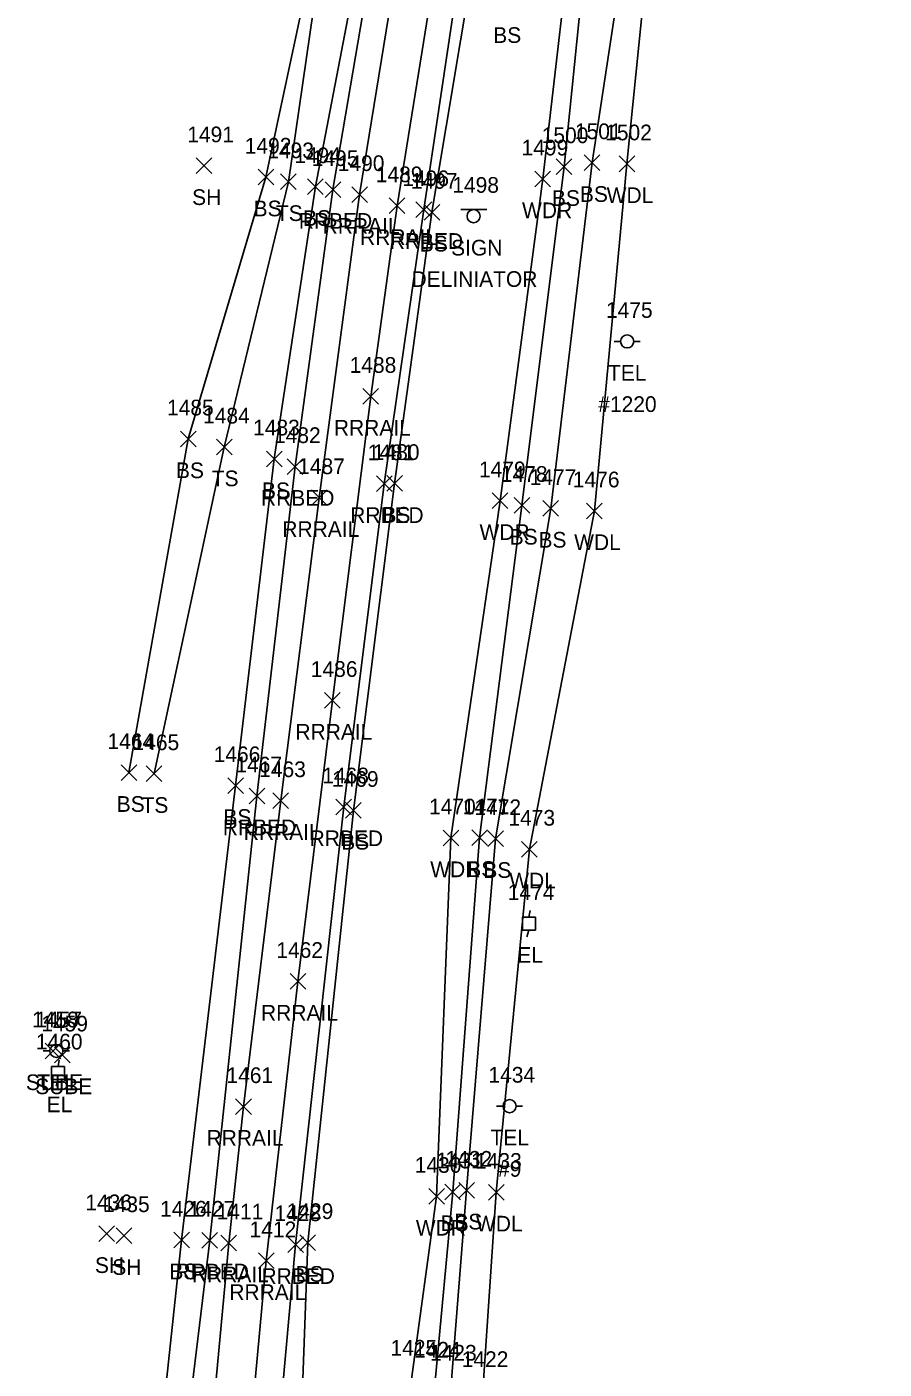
# Model space of a CAD drawing. Extents: x 1769141 to 1770817, y 735471 to 742405.
# Drawn here: x 1770142.5 to 1770251.8, y 741653.9 to 741825.1 of the extents above; entities that cross this region are included whole.
import ezdxf

# ---------------------------------------------------------------- set-up
doc = ezdxf.new("R2010")
doc.units = 0
for name, color, linetype in [('L_A', 7, 'Continuous'), ('L_I', 7, 'Continuous'), ('L_TIC', 7, 'Continuous'), ('LAWA', 7, 'Continuous'), ('LELB', 7, 'Continuous'), ('R_A', 7, 'Continuous'), ('R_I', 7, 'Continuous'), ('R_TIC', 7, 'Continuous'), ('RR', 7, 'Continuous'), ('RRB', 7, 'Continuous'), ('S_A', 7, 'Continuous'), ('S_C', 7, 'Continuous'), ('S_I', 7, 'Continuous'), ('SSGN', 7, 'Continuous'), ('U_A', 7, 'Continuous'), ('U_C', 7, 'Continuous'), ('U_I', 7, 'Continuous'), ('U_TIC', 7, 'Continuous'), ('UEPT', 7, 'Continuous'), ('UP', 7, 'Continuous')]:
    doc.layers.add(name, color=color, linetype=linetype)

msp = doc.modelspace()

# ---------------------------------------------------------------- linework, layer by layer
at = {"layer": 'L_TIC'}
for points in [[(1770213.61, 741806.75), (1770215.61, 741808.75)], [(1770215.61, 741806.75), (1770213.61, 741808.75)], [(1770164.12, 741806.35), (1770166.12, 741808.35)], [(1770166.12, 741806.35), (1770164.12, 741808.35)], [(1770210.04, 741806.24), (1770212.04, 741808.24)], [(1770212.04, 741806.24), (1770210.04, 741808.24)], [(1770218.05, 741806.6), (1770220.05, 741808.6)], [(1770220.05, 741806.6), (1770218.05, 741808.6)], [(1770172.01, 741804.91), (1770174.01, 741806.91)], [(1770174.01, 741804.91), (1770172.01, 741806.91)], [(1770174.88, 741804.31), (1770176.88, 741806.31)], [(1770176.88, 741804.31), (1770174.88, 741806.31)], [(1770178.32, 741803.69), (1770180.32, 741805.69)], [(1770180.32, 741803.69), (1770178.32, 741805.69)], [(1770207.31, 741804.67), (1770209.31, 741806.67)], [(1770209.31, 741804.67), (1770207.31, 741806.67)], [(1770193.19, 741800.42), (1770195.19, 741802.42)], [(1770195.19, 741800.42), (1770193.19, 741802.42)], [(1770162.11, 741771.52), (1770164.11, 741773.52)], [(1770164.11, 741771.52), (1770162.11, 741773.52)], [(1770166.7, 741770.49), (1770168.7, 741772.49)], [(1770168.7, 741770.49), (1770166.7, 741772.49)], [(1770173.08, 741768.97), (1770175.08, 741770.97)], [(1770175.08, 741768.97), (1770173.08, 741770.97)], [(1770188.43, 741765.84), (1770190.43, 741767.84)], [(1770190.43, 741765.84), (1770188.43, 741767.84)], [(1770201.88, 741763.64), (1770203.88, 741765.64)], [(1770203.88, 741763.64), (1770201.88, 741765.64)], [(1770204.66, 741763.05), (1770206.66, 741765.05)], [(1770206.66, 741763.05), (1770204.66, 741765.05)], [(1770208.33, 741762.66), (1770210.33, 741764.66)], [(1770210.33, 741762.66), (1770208.33, 741764.66)], [(1770213.9, 741762.35), (1770215.9, 741764.35)], [(1770215.9, 741762.35), (1770213.9, 741764.35)], [(1770154.56, 741728.97), (1770156.56, 741730.97)], [(1770156.56, 741728.97), (1770154.56, 741730.97)], [(1770157.75, 741728.84), (1770159.75, 741730.84)], [(1770159.75, 741728.84), (1770157.75, 741730.84)], [(1770168.16, 741727.31), (1770170.16, 741729.31)], [(1770170.16, 741727.31), (1770168.16, 741729.31)], [(1770183.18, 741724.16), (1770185.18, 741726.16)], [(1770185.18, 741724.16), (1770183.18, 741726.16)], [(1770195.6, 741720.64), (1770197.6, 741722.64)], [(1770197.6, 741720.64), (1770195.6, 741722.64)], [(1770199.25, 741720.67), (1770201.25, 741722.67)], [(1770201.25, 741720.67), (1770199.25, 741722.67)], [(1770201.3, 741720.55), (1770203.3, 741722.55)], [(1770203.3, 741720.55), (1770201.3, 741722.55)], [(1770205.62, 741719.21), (1770207.62, 741721.21)], [(1770207.62, 741719.21), (1770205.62, 741721.21)], [(1770193.77, 741674.94), (1770195.77, 741676.94)], [(1770195.77, 741674.94), (1770193.77, 741676.94)], [(1770195.84, 741675.51), (1770197.84, 741677.51)], [(1770197.84, 741675.51), (1770195.84, 741677.51)], [(1770197.6, 741675.72), (1770199.6, 741677.72)], [(1770199.6, 741675.72), (1770197.6, 741677.72)], [(1770201.39, 741675.46), (1770203.39, 741677.46)], [(1770203.39, 741675.46), (1770201.39, 741677.46)], [(1770151.73, 741670.17), (1770153.73, 741672.17)], [(1770153.73, 741670.17), (1770151.73, 741672.17)], [(1770153.94, 741669.93), (1770155.94, 741671.93)], [(1770155.94, 741669.93), (1770153.94, 741671.93)], [(1770161.27, 741669.36), (1770163.27, 741671.36)], [(1770163.27, 741669.36), (1770161.27, 741671.36)], [(1770177.36, 741669.05), (1770179.36, 741671.05)], [(1770179.36, 741669.05), (1770177.36, 741671.05)]]:
    msp.add_lwpolyline(points, dxfattribs=at)
at = {"layer": 'LAWA'}
for points in [[(1770200.67, 741651.18), (1770196.63, 741652), (1770194.58, 741652.38), (1770191.59, 741652.63), (1770194.77, 741675.94), (1770196.6, 741721.64), (1770202.88, 741764.64), (1770208.31, 741805.67), (1770212.68, 741843.55)], [(1770200.67, 741651.18), (1770202.39, 741676.46), (1770206.62, 741720.21), (1770214.9, 741763.35), (1770219.05, 741807.6), (1770222.48, 741841.68), (1770219.97, 741843.04), (1770214.71, 741843.41), (1770212.68, 741843.55)]]:
    msp.add_lwpolyline(points, dxfattribs=at)
at = {"layer": 'LELB'}
for points in [[(1770189.51, 741370.79), (1770192.33, 741421.87), (1770190.52, 741443.62), (1770191.25, 741465.52), (1770192.9, 741467.86), (1770192.23, 741494.22), (1770193.26, 741543.26), (1770192.21, 741598.2), (1770194.88, 741636.38), (1770196.63, 741652), (1770198.6, 741676.72), (1770202.3, 741721.55), (1770209.33, 741763.66), (1770214.61, 741807.75), (1770219.97, 741843.04), (1770223.09, 741876.08), (1770226.05, 741889.39), (1770243.39, 741887.35), (1770251.84, 741882.91)], [(1770189.82, 741481.43), (1770190.88, 741494.18), (1770191.42, 741543.22), (1770190.92, 741598.66), (1770192.66, 741636.32), (1770194.58, 741652.38), (1770196.84, 741676.51), (1770200.25, 741721.67), (1770205.66, 741764.05), (1770211.04, 741807.24), (1770214.71, 741843.41), (1770218.13, 741875.72), (1770220.67, 741890.47)], [(1770159.47, 741122.16), (1770155.88, 741129.72), (1770152.26, 741191.83), (1770148.79, 741250.94), (1770147.9, 741304.26), (1770146.46, 741364.5), (1770147.88, 741419.38), (1770149.7, 741479.08), (1770152.69, 741545.1), (1770155.76, 741599.64), (1770158.96, 741639.34), (1770162.27, 741670.36), (1770169.16, 741728.31), (1770174.08, 741769.97), (1770179.32, 741804.69), (1770187.63, 741847.88), (1770194.61, 741886.57)], [(1770170.72, 741118.89), (1770170.78, 741142.85), (1770168.08, 741192.95), (1770167.14, 741250.65), (1770163.56, 741305.09), (1770162.91, 741364.69), (1770162.95, 741418.42), (1770164.45, 741477.75), (1770168.47, 741544.61), (1770171.96, 741598.42), (1770177.16, 741637.54), (1770178.36, 741670.05), (1770184.18, 741725.16), (1770189.43, 741766.84), (1770194.19, 741801.42), (1770201.5, 741845.17), (1770207.42, 741883.86)], [(1770155.56, 741729.97), (1770163.11, 741772.52), (1770173.01, 741805.91), (1770182.25, 741849.08)], [(1770158.75, 741729.84), (1770167.7, 741771.49), (1770175.88, 741805.31), (1770182.25, 741849.08)]]:
    msp.add_lwpolyline(points, dxfattribs=at)
at = {"layer": 'R_TIC'}
for points in [[(1770180.57, 741803.32), (1770182.57, 741805.32)], [(1770182.57, 741803.32), (1770180.57, 741805.32)], [(1770183.96, 741802.68), (1770185.96, 741804.68)], [(1770185.96, 741802.68), (1770183.96, 741804.68)], [(1770188.73, 741801.26), (1770190.73, 741803.26)], [(1770190.73, 741801.26), (1770188.73, 741803.26)], [(1770192.15, 741800.76), (1770194.15, 741802.76)], [(1770194.15, 741800.76), (1770192.15, 741802.76)], [(1770185.38, 741776.95), (1770187.38, 741778.95)], [(1770187.38, 741776.95), (1770185.38, 741778.95)], [(1770175.74, 741768), (1770177.74, 741770)], [(1770177.74, 741768), (1770175.74, 741770)], [(1770187.11, 741765.81), (1770189.11, 741767.81)], [(1770189.11, 741765.81), (1770187.11, 741767.81)], [(1770178.82, 741764.03), (1770180.82, 741766.03)], [(1770180.82, 741764.03), (1770178.82, 741766.03)], [(1770180.49, 741738.18), (1770182.49, 741740.18)], [(1770182.49, 741738.18), (1770180.49, 741740.18)], [(1770170.87, 741725.99), (1770172.87, 741727.99)], [(1770172.87, 741725.99), (1770170.87, 741727.99)], [(1770173.9, 741725.4), (1770175.9, 741727.4)], [(1770175.9, 741725.4), (1770173.9, 741727.4)], [(1770181.94, 741724.6), (1770183.94, 741726.6)], [(1770183.94, 741724.6), (1770181.94, 741726.6)], [(1770176.09, 741702.35), (1770178.09, 741704.35)], [(1770178.09, 741702.35), (1770176.09, 741704.35)], [(1770169.16, 741686.39), (1770171.16, 741688.39)], [(1770171.16, 741686.39), (1770169.16, 741688.39)], [(1770164.85, 741669.35), (1770166.85, 741671.35)], [(1770166.85, 741669.35), (1770164.85, 741671.35)], [(1770167.28, 741668.99), (1770169.28, 741670.99)], [(1770169.28, 741668.99), (1770167.28, 741670.99)], [(1770175.8, 741668.78), (1770177.8, 741670.78)], [(1770177.8, 741668.78), (1770175.8, 741670.78)], [(1770172.06, 741666.73), (1770174.06, 741668.73)], [(1770174.06, 741666.73), (1770172.06, 741668.73)]]:
    msp.add_lwpolyline(points, dxfattribs=at)
at = {"layer": 'RR'}
for points in [[(1770166.02, 741645.78), (1770168.28, 741669.99), (1770170.16, 741687.39), (1770174.9, 741726.4), (1770179.82, 741765.03), (1770184.96, 741803.68), (1770190.21, 741836.07), (1770195.69, 741868.56), (1770199.22, 741889.17), (1770209.87, 741946.53), (1770217, 741981.75), (1770223.18, 742009.88), (1770228.86, 742035.21), (1770233.42, 742054.72)], [(1770169.48, 741629), (1770173.06, 741667.73), (1770177.09, 741703.35), (1770181.49, 741739.18), (1770186.38, 741777.95), (1770189.73, 741802.26), (1770194.57, 741832.07), (1770199.51, 741861.73), (1770205.13, 741894.27), (1770209.73, 741919.85), (1770215.58, 741950.2), (1770216.86, 741956.06), (1770219.87, 741971.28), (1770226.9, 742003.73), (1770230.49, 742019.98), (1770231.83, 742026.33), (1770232.94, 742031.03), (1770234.04, 742035.58), (1770238.5, 742054.13)]]:
    msp.add_lwpolyline(points, dxfattribs=at)
at = {"layer": 'RRB'}
for points in [[(1770159.47, 741122.16), (1770157.22, 741138.41), (1770154.83, 741192.11), (1770151.88, 741250.64), (1770151.59, 741304.35), (1770150.34, 741364.24), (1770150.63, 741419.36), (1770151.12, 741479.07), (1770155.02, 741545.1), (1770158.66, 741599.97), (1770162.08, 741639.22), (1770165.85, 741670.35), (1770171.87, 741726.99), (1770176.74, 741769), (1770181.57, 741804.32), (1770188.88, 741847.51), (1770194.61, 741886.57), (1770198.24, 741898.62)], [(1770170.72, 741118.89), (1770169.25, 741143.07), (1770166.39, 741192.95), (1770164.02, 741250.29), (1770162.37, 741304.75), (1770161.63, 741364.62), (1770161.73, 741418.13), (1770163.48, 741477.78), (1770166.12, 741544.52), (1770169.96, 741598.79), (1770173.92, 741637.73), (1770176.8, 741669.78), (1770182.94, 741725.6), (1770188.11, 741766.81), (1770193.15, 741801.76), (1770199.69, 741845.61), (1770207.42, 741883.86)]]:
    msp.add_lwpolyline(points, dxfattribs=at)
at = {"layer": 'SSGN'}
for p, q in [((1770197.85, 741801.77), (1770201.18, 741801.77)), ((1770199.49, 741800.93), (1770199.49, 741800.93))]:
    msp.add_line(p, q, dxfattribs=at)
msp.add_circle((1770199.49, 741800.93), 0.833, dxfattribs=at)
at = {"layer": 'U_TIC'}
for points in [[(1770144.88, 741693.49), (1770146.88, 741695.49)], [(1770146.88, 741693.49), (1770144.88, 741695.49)], [(1770146.08, 741692.97), (1770148.08, 741694.97)], [(1770148.08, 741692.97), (1770146.08, 741694.97)]]:
    msp.add_lwpolyline(points, dxfattribs=at)
at = {"layer": 'UEPT'}
for p, q in [((1770205.71, 741709.88), (1770205.71, 741711.55)), ((1770205.71, 741711.55), (1770207.37, 741711.55)), ((1770206.71, 741712.38), (1770206.54, 741711.55)), ((1770207.37, 741711.55), (1770207.37, 741709.88)), ((1770207.37, 741709.88), (1770205.71, 741709.88)), ((1770206.29, 741709.05), (1770206.54, 741709.88)), ((1770206.54, 741710.72), (1770206.54, 741710.72)), ((1770145.68, 741690.83), (1770145.68, 741692.5)), ((1770145.68, 741692.5), (1770147.35, 741692.5)), ((1770146.68, 741693.33), (1770146.52, 741692.5)), ((1770147.35, 741692.5), (1770147.35, 741690.83)), ((1770147.35, 741690.83), (1770145.68, 741690.83)), ((1770146.27, 741690), (1770146.52, 741690.83)), ((1770146.52, 741691.67), (1770146.52, 741691.67))]:
    msp.add_line(p, q, dxfattribs=at)
at = {"layer": 'UP'}
for p, q in [((1770217.41, 741784.96), (1770218.23, 741784.96)), ((1770219.07, 741784.96), (1770219.07, 741784.96)), ((1770220.73, 741784.96), (1770219.9, 741784.96)), ((1770219.9, 741784.96), (1770219.9, 741784.96)), ((1770220.73, 741784.96), (1770220.73, 741784.96)), ((1770144.64, 741694.48), (1770145.47, 741694.48)), ((1770146.3, 741694.48), (1770146.3, 741694.48)), ((1770147.97, 741694.48), (1770147.13, 741694.48)), ((1770147.13, 741694.48), (1770147.13, 741694.48)), ((1770147.97, 741694.48), (1770147.97, 741694.48)), ((1770202.42, 741687.43), (1770203.24, 741687.43)), ((1770204.08, 741687.44), (1770204.08, 741687.44)), ((1770205.74, 741687.44), (1770204.91, 741687.44)), ((1770204.91, 741687.44), (1770204.91, 741687.44)), ((1770205.74, 741687.44), (1770205.74, 741687.44))]:
    msp.add_line(p, q, dxfattribs=at)
for centre in [(1770219.07, 741784.96), (1770146.3, 741694.48), (1770204.08, 741687.44)]:
    msp.add_circle(centre, 0.833, dxfattribs=at)

# ---------------------------------------------------------------- texts
at = {"layer": 'L_A'}
for s, p in [('BS', (1770202, 741823.02)), ('SH', (1770163.61, 741802.35)), ('BS', (1770209.48, 741802.24)), ('BS', (1770213.05, 741802.75)), ('WDL', (1770216.46, 741802.6)), ('BS', (1770171.45, 741800.91)), ('TS', (1770174.29, 741800.31)), ('WDR', (1770205.67, 741800.67)), ('BS', (1770177.76, 741799.69)), ('BS', (1770192.63, 741796.42)), ('BS', (1770161.55, 741767.52)), ('TS', (1770166.11, 741766.49)), ('BS', (1770172.52, 741764.97)), ('BS', (1770187.87, 741761.84)), ('WDR', (1770200.25, 741759.64)), ('BS', (1770204.1, 741759.05)), ('BS', (1770207.77, 741758.66)), ('WDL', (1770212.32, 741758.35)), ('BS', (1770154, 741724.97)), ('TS', (1770157.16, 741724.84)), ('BS', (1770167.6, 741723.31)), ('BS', (1770182.62, 741720.16)), ('WDR', (1770193.97, 741716.64)), ('BS', (1770198.69, 741716.67)), ('BS', (1770200.74, 741716.55)), ('WDL', (1770204.04, 741715.21)), ('BS', (1770195.28, 741671.51)), ('BS', (1770197.04, 741671.72)), ('WDL', (1770199.8, 741671.46)), ('WDR', (1770192.13, 741670.94)), ('SH', (1770151.22, 741666.17)), ('SH', (1770153.43, 741665.93)), ('BS', (1770160.71, 741665.36)), ('BS', (1770176.8, 741665.05))]:
    msp.add_text(s, height=2, dxfattribs=at).set_placement(p)
at = {"layer": 'L_I'}
for s, p in [('1491', (1770162.99, 741810.35)), ('1500', (1770208.18, 741810.24)), ('1501', (1770212.41, 741810.75)), ('1502', (1770216.27, 741810.6)), ('1492', (1770170.32, 741808.91)), ('1499', (1770205.61, 741808.67)), ('1493', (1770173.19, 741808.31)), ('1494', (1770176.63, 741807.69)), ('1497', (1770191.5, 741804.42)), ('1485', (1770160.41, 741775.52)), ('1484', (1770165.01, 741774.49)), ('1483', (1770171.39, 741772.97)), ('1480', (1770186.65, 741769.84)), ('1479', (1770200.18, 741767.64)), ('1478', (1770202.97, 741767.05)), ('1477', (1770206.64, 741766.66)), ('1476', (1770212.15, 741766.35)), ('1464', (1770152.82, 741732.97)), ('1465', (1770156.01, 741732.84)), ('1466', (1770166.36, 741731.31)), ('1469', (1770181.43, 741728.16)), ('1470', (1770193.82, 741724.64)), ('1471', (1770198.12, 741724.67)), ('1472', (1770199.6, 741724.55)), ('1473', (1770203.93, 741723.21)), ('1430', (1770191.99, 741678.94)), ('1431', (1770194.71, 741679.51)), ('1432', (1770195.91, 741679.72)), ('1433', (1770199.69, 741679.46)), ('1436', (1770149.99, 741674.17)), ('1435', (1770152.25, 741673.93)), ('1426', (1770159.52, 741673.36)), ('1429', (1770175.66, 741673.05)), ('1425', (1770188.9, 741655.63)), ('1425', (1770188.9, 741655.63)), ('1424', (1770191.89, 741655.38)), ('1424', (1770191.89, 741655.38)), ('1423', (1770193.94, 741655)), ('1423', (1770193.94, 741655)), ('1422', (1770197.98, 741654.18)), ('1422', (1770197.98, 741654.18)), ('1422', (1770197.98, 741654.18))]:
    msp.add_text(s, height=2, dxfattribs=at).set_placement(p)
at = {"layer": 'R_A'}
for s, p in [('RRBED', (1770177.21, 741799.32)), ('RRRAIL', (1770180.25, 741798.68)), ('RRRAIL', (1770185.02, 741797.26)), ('RRBED', (1770188.8, 741796.76)), ('RRRAIL', (1770181.68, 741772.95)), ('RRBED', (1770172.39, 741764)), ('RRBED', (1770183.76, 741761.81)), ('RRRAIL', (1770175.11, 741760.03)), ('RRRAIL', (1770176.78, 741734.18)), ('RRBED', (1770167.52, 741721.99)), ('RRRAIL', (1770170.19, 741721.4)), ('RRBED', (1770178.59, 741720.6)), ('RRRAIL', (1770172.39, 741698.35)), ('RRRAIL', (1770165.45, 741682.39)), ('RRBED', (1770161.49, 741665.35)), ('RRRAIL', (1770163.58, 741664.99)), ('RRBED', (1770172.45, 741664.78)), ('RRRAIL', (1770168.35, 741662.73))]:
    msp.add_text(s, height=2, dxfattribs=at).set_placement(p)
at = {"layer": 'R_I'}
for s, p in [('1495', (1770178.87, 741807.32)), ('1490', (1770182.18, 741806.68)), ('1489', (1770187.03, 741805.26)), ('1496', (1770190.41, 741804.76)), ('1488', (1770183.69, 741780.95)), ('1482', (1770174.05, 741772)), ('1481', (1770185.99, 741769.81)), ('1487', (1770177.13, 741768.03)), ('1486', (1770178.74, 741742.18)), ('1467', (1770169.13, 741729.99)), ('1463', (1770172.16, 741729.4)), ('1468', (1770180.2, 741728.6)), ('1462', (1770174.35, 741706.35)), ('1461', (1770167.99, 741690.39)), ('1427', (1770163.15, 741673.35)), ('1411', (1770166.73, 741672.99)), ('1428', (1770174.11, 741672.78)), ('1412', (1770170.93, 741670.73))]:
    msp.add_text(s, height=2, dxfattribs=at).set_placement(p)
at = {"layer": 'S_A'}
msp.add_text('SIGN', height=2, dxfattribs=at).set_placement((1770196.63, 741795.91))
at = {"layer": 'S_C'}
msp.add_text('DELINIATOR', height=2, dxfattribs=at).set_placement((1770191.58, 741791.91))
at = {"layer": 'S_I'}
msp.add_text('1498', height=2, dxfattribs=at).set_placement((1770196.78, 741803.91))
at = {"layer": 'U_A'}
for s, p in [('TEL', (1770216.63, 741779.96)), ('EL', (1770205.08, 741705.72)), ('SUBE', (1770142.42, 741689.49)), ('SUBE', (1770143.61, 741688.97)), ('TEL', (1770143.86, 741689.48)), ('EL', (1770145.05, 741686.67)), ('TEL', (1770201.64, 741682.44))]:
    msp.add_text(s, height=2, dxfattribs=at).set_placement(p)
at = {"layer": 'U_C'}
for s, p in [('#1220', (1770215.39, 741775.96)), ('#9', (1770202.61, 741678.44))]:
    msp.add_text(s, height=2, dxfattribs=at).set_placement(p)
at = {"layer": 'U_I'}
for s, p in [('1475', (1770216.37, 741787.96)), ('1474', (1770203.85, 741713.72)), ('1458', (1770143.19, 741697.49)), ('1457', (1770143.61, 741697.48)), ('1459', (1770144.38, 741696.97)), ('1460', (1770143.69, 741694.67)), ('1434', (1770201.39, 741690.44))]:
    msp.add_text(s, height=2, dxfattribs=at).set_placement(p)

doc.saveas('drawing.dxf')
